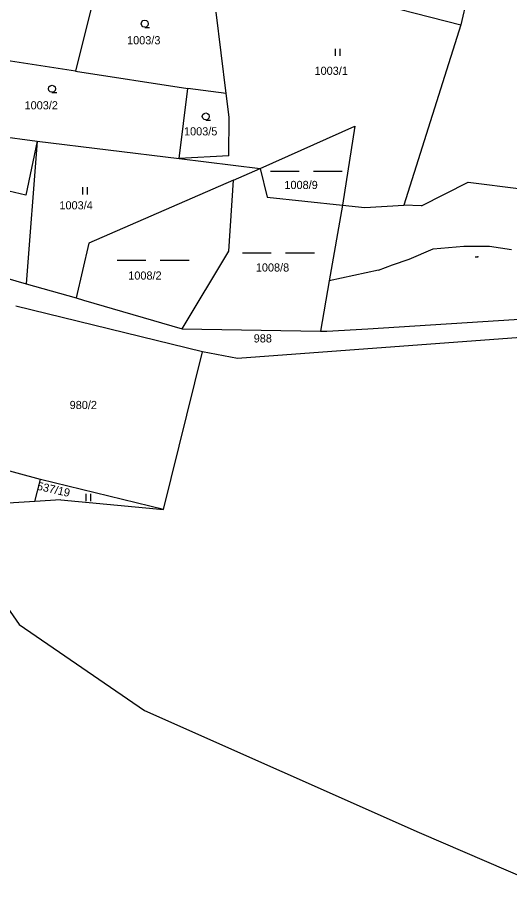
# Model space of a CAD drawing. Extents: x -852001 to -842497, y -1063614 to -1052182.
# Drawn here: x -844365.4 to -844262.9, y -1061709 to -1061526.1 of the extents above; entities that cross this region are included whole.
import ezdxf

# ---------------------------------------------------------------- set-up
doc = ezdxf.new("R2010")
doc.units = 0
for name, color, linetype in [('Default', 7, 'Continuous'), ('KN_HRANICE', 7, 'Continuous'), ('KN_KULTURY', 7, 'Continuous'), ('KN_PARCELY', 7, 'Continuous'), ('KN_SLUCKY', 7, 'Continuous')]:
    doc.layers.add(name, color=color, linetype=linetype)

# ---------------------------------------------------------------- blocks, each defined once
blk = doc.blocks.new('304')
at = {"layer": 'Default'}
blk.add_lwpolyline([(0, 0), (-0.38, 0.1), (-0.65, 0.37), (-0.75, 0.74), (-0.65, 1.11), (-0.38, 1.38), (-0.01, 1.48), (0.36, 1.38), (0.63, 1.11), (0.73, 0.73), (0.63, 0.35), (0.36, 0.08), (-0.02, -0.02), (0.98, -0.02)], dxfattribs=at)
blk = doc.blocks.new('306')
at = {"layer": 'Default'}
for p, q in [((-0.5, 1.5), (-0.5, 0)), ((0.5, 0), (0.5, 1.5))]:
    blk.add_line(p, q, dxfattribs=at)
blk = doc.blocks.new('803')
at = {"layer": 'Default'}
for p, q in [((-7.5, 0), (-1.5, 0)), ((1.5, 0), (7.5, 0))]:
    blk.add_line(p, q, dxfattribs=at)
blk = doc.blocks.new('1060')
at = {"layer": 'Default'}
blk.add_line((-0.3, 0), (0.3, 0), dxfattribs=at)
blk.add_lwpolyline([(0.18, 0.04), (0.3, 0), (0.18, -0.04)], dxfattribs=at)

msp = doc.modelspace()

# ---------------------------------------------------------------- linework, layer by layer
at = {"layer": 'KN_HRANICE'}
for p, q in [((-844325.04, -1061514.23), (-844273.04, -1061527.65)), ((-844325.04, -1061514.23), (-844273.04, -1061527.65)), ((-844349.36, -1061521.16), (-844353.34, -1061537.33)), ((-844349.36, -1061521.16), (-844353.34, -1061537.33)), ((-844271.27, -1061519.86), (-844273.04, -1061527.65)), ((-844271.27, -1061519.86), (-844273.04, -1061527.65)), ((-844321.96, -1061541.94), (-844324.04, -1061525.01)), ((-844321.96, -1061541.94), (-844324.04, -1061525.01)), ((-844273.04, -1061527.65), (-844284.89, -1061565.27)), ((-844273.04, -1061527.65), (-844284.89, -1061565.27)), ((-844353.34, -1061537.33), (-844388.92, -1061531.86)), ((-844353.34, -1061537.33), (-844388.92, -1061531.86)), ((-844353.34, -1061537.33), (-844329.92, -1061540.93)), ((-844353.34, -1061537.33), (-844329.92, -1061540.93)), ((-844331.78, -1061555.55), (-844329.92, -1061540.93)), ((-844331.78, -1061555.55), (-844329.92, -1061540.93)), ((-844321.96, -1061541.94), (-844329.92, -1061540.93)), ((-844321.96, -1061541.94), (-844329.92, -1061540.93)), ((-844321.35, -1061546.91), (-844321.96, -1061541.94)), ((-844321.35, -1061546.91), (-844321.96, -1061541.94)), ((-844321.41, -1061554.97), (-844321.35, -1061546.91)), ((-844321.41, -1061554.97), (-844321.35, -1061546.91)), ((-844390.76, -1061547.96), (-844361.35, -1061551.88)), ((-844390.76, -1061547.96), (-844361.35, -1061551.88)), ((-844314.87, -1061557.58), (-844295.15, -1061548.77)), ((-844314.87, -1061557.58), (-844295.15, -1061548.77)), ((-844295.15, -1061548.77), (-844297.72, -1061565.27)), ((-844295.15, -1061548.77), (-844297.72, -1061565.27)), ((-844361.35, -1061551.88), (-844363.72, -1061563.16)), ((-844361.35, -1061551.88), (-844363.72, -1061563.16)), ((-844361.35, -1061551.88), (-844363.66, -1061581.64)), ((-844361.35, -1061551.88), (-844363.66, -1061581.64)), ((-844361.35, -1061551.88), (-844331.78, -1061555.55)), ((-844361.35, -1061551.88), (-844331.78, -1061555.55)), ((-844321.41, -1061554.97), (-844331.78, -1061555.55)), ((-844321.41, -1061554.97), (-844331.78, -1061555.55)), ((-844331.78, -1061555.55), (-844314.87, -1061557.58)), ((-844331.78, -1061555.55), (-844314.87, -1061557.58)), ((-844363.72, -1061563.16), (-844391.89, -1061556.58)), ((-844363.72, -1061563.16), (-844391.89, -1061556.58)), ((-844320.4, -1061560.02), (-844314.87, -1061557.58)), ((-844320.4, -1061560.02), (-844314.87, -1061557.58)), ((-844314.87, -1061557.58), (-844313.41, -1061563.61)), ((-844314.87, -1061557.58), (-844313.41, -1061563.61)), ((-844320.4, -1061560.02), (-844350.6, -1061573.17)), ((-844320.4, -1061560.02), (-844350.6, -1061573.17)), ((-844321.39, -1061574.83), (-844320.4, -1061560.02)), ((-844321.39, -1061574.83), (-844320.4, -1061560.02)), ((-844281.26, -1061565.4), (-844271.49, -1061560.45)), ((-844281.26, -1061565.4), (-844271.49, -1061560.45)), ((-844271.49, -1061560.45), (-844260.43, -1061561.87)), ((-844271.49, -1061560.45), (-844260.43, -1061561.87)), ((-844313.41, -1061563.61), (-844297.72, -1061565.27)), ((-844313.41, -1061563.61), (-844297.72, -1061565.27)), ((-844297.72, -1061565.27), (-844300.47, -1061581.03)), ((-844297.72, -1061565.27), (-844300.47, -1061581.03)), ((-844297.72, -1061565.27), (-844293.03, -1061565.76)), ((-844297.72, -1061565.27), (-844293.03, -1061565.76)), ((-844293.03, -1061565.76), (-844284.89, -1061565.27)), ((-844293.03, -1061565.76), (-844284.89, -1061565.27)), ((-844281.26, -1061565.4), (-844284.89, -1061565.27)), ((-844281.26, -1061565.4), (-844284.89, -1061565.27)), ((-844403.95, -1061570.2), (-844363.66, -1061581.64)), ((-844403.95, -1061570.2), (-844363.66, -1061581.64)), ((-844350.6, -1061573.17), (-844353.2, -1061584.61)), ((-844350.6, -1061573.17), (-844353.2, -1061584.61)), ((-844331.11, -1061591.08), (-844321.39, -1061574.83)), ((-844331.11, -1061591.08), (-844321.39, -1061574.83)), ((-844363.66, -1061581.64), (-844353.2, -1061584.61)), ((-844363.66, -1061581.64), (-844353.2, -1061584.61)), ((-844300.47, -1061581.03), (-844302.31, -1061591.53)), ((-844300.47, -1061581.03), (-844302.31, -1061591.53)), ((-844353.2, -1061584.61), (-844351.68, -1061585.04)), ((-844353.2, -1061584.61), (-844351.68, -1061585.04)), ((-844351.68, -1061585.04), (-844331.11, -1061591.08)), ((-844351.68, -1061585.04), (-844331.11, -1061591.08)), ((-844326.87, -1061595.82), (-844365.77, -1061586.33)), ((-844326.87, -1061595.82), (-844365.77, -1061586.33)), ((-844292.4, -1061591.06), (-844254.72, -1061588.66)), ((-844292.4, -1061591.06), (-844254.72, -1061588.66)), ((-844331.11, -1061591.08), (-844302.31, -1061591.53)), ((-844331.11, -1061591.08), (-844302.31, -1061591.53)), ((-844300.94, -1061591.55), (-844292.4, -1061591.06)), ((-844300.94, -1061591.55), (-844292.4, -1061591.06)), ((-844255.5, -1061592.46), (-844319.6, -1061597.27)), ((-844255.5, -1061592.46), (-844319.6, -1061597.27)), ((-844302.31, -1061591.53), (-844300.94, -1061591.55)), ((-844302.31, -1061591.53), (-844300.94, -1061591.55)), ((-844334.99, -1061628.71), (-844326.87, -1061595.82)), ((-844334.99, -1061628.71), (-844326.87, -1061595.82)), ((-844319.6, -1061597.27), (-844326.87, -1061595.82)), ((-844319.6, -1061597.27), (-844326.87, -1061595.82)), ((-844360.67, -1061622.48), (-844374.13, -1061618.87)), ((-844360.67, -1061622.48), (-844374.13, -1061618.87)), ((-844361.86, -1061627.06), (-844360.67, -1061622.48)), ((-844361.86, -1061627.06), (-844360.67, -1061622.48)), ((-844334.99, -1061628.71), (-844360.67, -1061622.48)), ((-844334.99, -1061628.71), (-844360.67, -1061622.48)), ((-844361.86, -1061627.06), (-844378.77, -1061628.06)), ((-844361.86, -1061627.06), (-844378.77, -1061628.06)), ((-844356.45, -1061626.74), (-844361.86, -1061627.06)), ((-844356.45, -1061626.74), (-844361.86, -1061627.06)), ((-844356.45, -1061626.74), (-844334.99, -1061628.71)), ((-844356.45, -1061626.74), (-844334.99, -1061628.71)), ((-844376.04, -1061637.09), (-844365.11, -1061652.71)), ((-844376.04, -1061637.09), (-844365.11, -1061652.71)), ((-844365.11, -1061652.71), (-844338.96, -1061670.68)), ((-844365.11, -1061652.71), (-844338.96, -1061670.68)), ((-844338.96, -1061670.68), (-844281.72, -1061696.14)), ((-844338.96, -1061670.68), (-844281.72, -1061696.14)), ((-844281.72, -1061696.14), (-844251.79, -1061709.03)), ((-844281.72, -1061696.14), (-844251.79, -1061709.03))]:
    msp.add_line(p, q, dxfattribs=at)
at = {"layer": 'KN_SLUCKY'}
for p, q in [((-844283.8, -1061576.51), (-844278.78, -1061574.38)), ((-844283.8, -1061576.51), (-844278.78, -1061574.38)), ((-844278.78, -1061574.38), (-844272.39, -1061573.77)), ((-844278.78, -1061574.38), (-844272.39, -1061573.77)), ((-844272.39, -1061573.77), (-844267.07, -1061573.77)), ((-844272.39, -1061573.77), (-844267.07, -1061573.77)), ((-844267.07, -1061573.77), (-844262.5, -1061574.53)), ((-844267.07, -1061573.77), (-844262.5, -1061574.53)), ((-844290.2, -1061578.79), (-844287.3, -1061577.72)), ((-844290.2, -1061578.79), (-844287.3, -1061577.72)), ((-844287.3, -1061577.72), (-844283.8, -1061576.51)), ((-844287.3, -1061577.72), (-844283.8, -1061576.51)), ((-844290.2, -1061578.79), (-844300.47, -1061581.03)), ((-844290.2, -1061578.79), (-844300.47, -1061581.03))]:
    msp.add_line(p, q, dxfattribs=at)

# ---------------------------------------------------------------- block references
at = {"layer": 'KN_KULTURY'}
for name, p in [('304', (-844338.91, -1061528.14)), ('304', (-844338.91, -1061528.14)), ('306', (-844298.71, -1061534.13)), ('306', (-844298.71, -1061534.13)), ('304', (-844358.24, -1061541.71)), ('304', (-844358.24, -1061541.71)), ('304', (-844326.19, -1061547.48)), ('304', (-844326.19, -1061547.48)), ('803', (-844305.24, -1061558.19)), ('803', (-844305.24, -1061558.19)), ('306', (-844351.38, -1061563)), ('306', (-844351.38, -1061563)), ('803', (-844311.05, -1061575.18)), ('803', (-844311.05, -1061575.18)), ('803', (-844337.19, -1061576.75)), ('803', (-844337.19, -1061576.75)), ('306', (-844350.69, -1061626.99)), ('306', (-844350.69, -1061626.99))]:
    msp.add_blockref(name, p, dxfattribs=at)
at = {"layer": 'KN_PARCELY', "rotation": 2.979381}
msp.add_blockref('1060', (-844269.71, -1061576.03), dxfattribs=at)
msp.add_blockref('1060', (-844269.71, -1061576.03), dxfattribs=at)

# ---------------------------------------------------------------- texts
at = {"layer": 'KN_PARCELY'}
for s, p in [('1003/3', (-844342.61, -1061531.7)), ('1003/3', (-844342.61, -1061531.7)), ('1003/1', (-844303.53, -1061538.07)), ('1003/1', (-844303.53, -1061538.07)), ('1003/2', (-844363.98, -1061545.27)), ('1003/2', (-844363.98, -1061545.27)), ('1003/5', (-844330.74, -1061550.7)), ('1003/5', (-844330.74, -1061550.7)), ('1008/9', (-844309.81, -1061561.88)), ('1008/9', (-844309.81, -1061561.88)), ('1003/4', (-844356.71, -1061566.13)), ('1003/4', (-844356.71, -1061566.13)), ('1008/8', (-844315.77, -1061579.1)), ('1008/8', (-844315.77, -1061579.1)), ('1008/2', (-844342.36, -1061580.78)), ('1008/2', (-844342.36, -1061580.78)), ('988', (-844316.21, -1061593.89)), ('988', (-844316.21, -1061593.89)), ('980/2', (-844354.58, -1061607.78)), ('980/2', (-844354.58, -1061607.78))]:
    msp.add_text(s, height=1.7, dxfattribs=at).set_placement(p)
msp.add_text('537/19', height=1.7, rotation=347.155, dxfattribs=at).set_placement((-844361.51, -1061624.59))
msp.add_text('537/19', height=1.7, rotation=347.155, dxfattribs=at).set_placement((-844361.51, -1061624.59))

doc.saveas('drawing.dxf')
